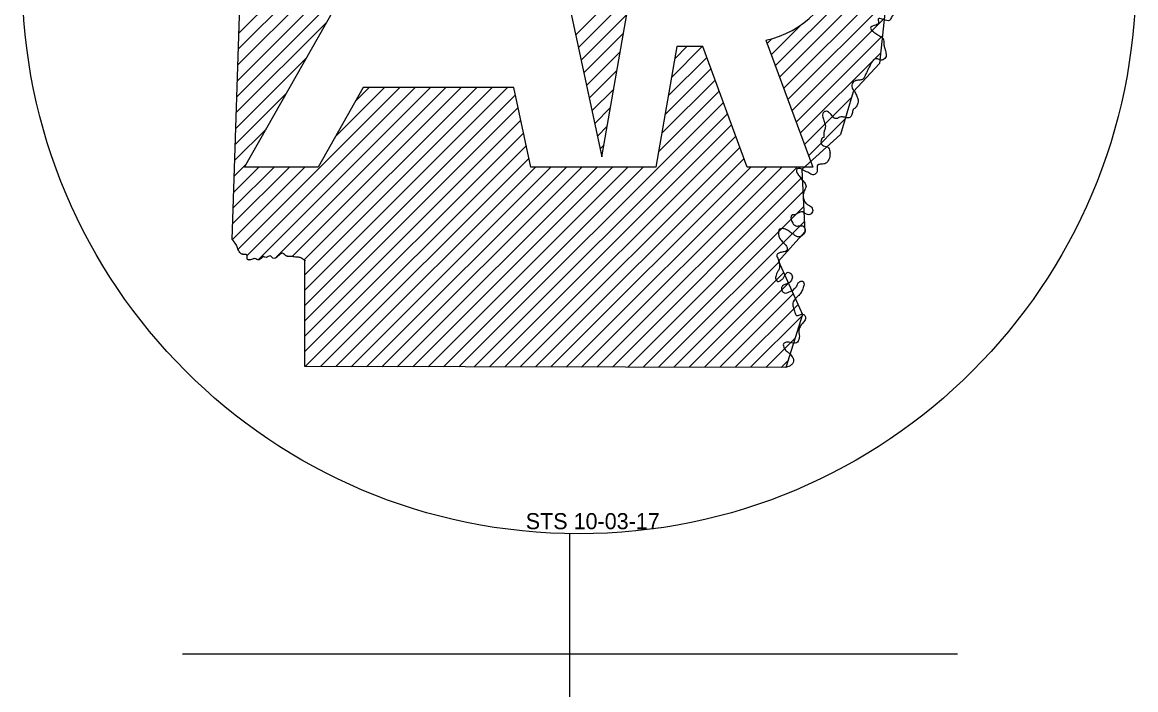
# Model space of a CAD drawing. Extents: x 6028647 to 6035072, y 5366486 to 5368495.
# Drawn here: x 6030902 to 6030966, y 5366837.7 to 5366876 of the extents above; entities that cross this region are included whole.
import ezdxf

# ---------------------------------------------------------------- set-up
doc = ezdxf.new("R2010")
doc.units = 0
doc.layers.add('R_Draft', color=7, linetype='Continuous')
doc.layers.add('R_Water Annot', color=7, linetype='Continuous')

msp = doc.modelspace()

# ---------------------------------------------------------------- linework, layer by layer
at = {"layer": 'R_Draft'}
for p, q in [((6030914.803, 5366867.71), (6030927.128, 5366889.476)), ((6030944.738, 5366875.002), (6030947.432, 5366867.71)), ((6030941.115, 5366874.633), (6030939.632, 5366874.633)), ((6030943.672, 5366867.71), (6030941.115, 5366874.633)), ((6030921.618, 5366872.277), (6030919.032, 5366867.71)), ((6030930.275, 5366872.277), (6030921.618, 5366872.277)), ((6030919.032, 5366867.71), (6030914.803, 5366867.71)), ((6030938.425, 5366867.71), (6030931.252, 5366867.71)), ((6030947.432, 5366867.71), (6030943.672, 5366867.71)), ((6030933.491, 5366765.514), (6030933.491, 5366846.638)), ((6030911.237, 5366839.743), (6030955.741, 5366839.743))]:
    msp.add_line(p, q, dxfattribs=at)
for points in [[(6030914.086, 5366863.555), (6030914.765, 5366884.006), (6030913.204, 5366896.534)], [(6030958.388, 5366891.28), (6030959.443, 5366890.179), (6030956.813, 5366888.017), (6030957.097, 5366885.835), (6030954.842, 5366884.348), (6030955.614, 5366880.992), (6030953.875, 5366879.406), (6030953.72, 5366877.681), (6030951.606, 5366876.921), (6030951.277, 5366873.668), (6030949.758, 5366872.041), (6030949.024, 5366869.591), (6030946.812, 5366867.566), (6030946.979, 5366863.993), (6030945.476, 5366862.309), (6030946.846, 5366859.243), (6030945.897, 5366856.198)], [(6030930.79, 5366889.476), (6030935.324, 5366868.292), (6030938.224, 5366884.936)], [(6030914.089, 5366863.553), (6030914.552, 5366877.585)], [(6030939.632, 5366874.633), (6030938.425, 5366867.71)], [(6030931.252, 5366867.71), (6030930.275, 5366872.277)], [(6030945.897, 5366856.198), (6030918.27, 5366856.244), (6030918.255, 5366862.342)], [(6030945.895, 5366856.195), (6030918.27, 5366856.244), (6030918.258, 5366862.343)]]:
    msp.add_lwpolyline(points, dxfattribs=at)
msp.add_ellipse((6030934.009, 5366878.608), major_axis=(31.975, 0), ratio=0.999976, dxfattribs=at)
msp.add_ellipse((6030943.601, 5366880.414), major_axis=(-5.53, 0), ratio=0.999987, start_param=1.777838, end_param=4.099264, dxfattribs=at)
for points in [[(6030952.244, 5366876.557), (6030951.982, 5366876.358), (6030951.862, 5366876.149), (6030951.192, 5366876.209), (6030951.21, 5366875.974), (6030950.971, 5366875.85), (6030950.759, 5366875.697), (6030950.88, 5366875.514), (6030951.107, 5366875.349), (6030951.334, 5366875.223), (6030951.475, 5366875.096), (6030951.511, 5366874.781), (6030951.553, 5366874.588), (6030951.627, 5366874.313), (6030951.657, 5366874.129), (6030951.521, 5366873.906), (6030951.361, 5366873.858), (6030951.199, 5366873.912), (6030951.003, 5366873.925), (6030950.845, 5366873.778), (6030950.731, 5366873.564), (6030950.62, 5366873.349), (6030950.534, 5366873.171), (6030950.445, 5366872.973), (6030950.287, 5366872.745), (6030950.086, 5366872.712), (6030949.842, 5366872.652), (6030949.698, 5366872.489), (6030949.722, 5366872.207), (6030949.857, 5366872.02), (6030949.962, 5366871.783), (6030950.034, 5366871.581), (6030950.004, 5366871.326), (6030949.898, 5366871.133), (6030949.76, 5366871.02), (6030949.698, 5366870.782), (6030949.598, 5366870.597), (6030949.51, 5366870.541), (6030949.33, 5366870.56), (6030949.135, 5366870.594), (6030948.969, 5366870.579), (6030948.812, 5366870.496), (6030948.65, 5366870.55), (6030948.484, 5366870.728), (6030948.348, 5366870.865), (6030948.197, 5366870.919), (6030948.036, 5366870.837), (6030948.012, 5366870.584), (6030948.088, 5366870.332), (6030948.154, 5366869.982), (6030948.088, 5366869.775), (6030948.065, 5366869.42)], [(6030948.065, 5366869.42), (6030948.045, 5366869.412), (6030947.911, 5366869.242), (6030947.985, 5366868.975), (6030948.279, 5366868.871), (6030948.414, 5366868.616), (6030948.421, 5366868.391), (6030948.326, 5366868.08), (6030948.188, 5366867.934), (6030947.926, 5366867.873), (6030947.724, 5366867.837), (6030947.695, 5366867.491), (6030947.6, 5366867.318), (6030947.444, 5366867.266), (6030947.216, 5366867.377), (6030947.079, 5366867.435), (6030946.915, 5366867.509), (6030946.703, 5366867.629), (6030946.542, 5366867.609), (6030946.589, 5366867.28), (6030946.604, 5366867.266), (6030946.787, 5366867.016), (6030946.963, 5366866.819), (6030947.048, 5366866.586)], [(6030948.065, 5366869.42), (6030948.045, 5366869.412), (6030947.911, 5366869.242), (6030947.985, 5366868.975), (6030948.279, 5366868.871), (6030948.414, 5366868.616), (6030948.421, 5366868.391), (6030948.326, 5366868.08), (6030948.188, 5366867.934), (6030947.926, 5366867.873), (6030947.724, 5366867.837), (6030947.695, 5366867.491), (6030947.6, 5366867.318), (6030947.444, 5366867.266), (6030947.216, 5366867.377), (6030947.079, 5366867.435), (6030946.915, 5366867.509), (6030946.703, 5366867.629), (6030946.542, 5366867.609), (6030946.589, 5366867.28), (6030946.604, 5366867.266), (6030946.787, 5366867.016), (6030946.963, 5366866.819), (6030947.048, 5366866.586)], [(6030947.048, 5366866.586), (6030946.977, 5366866.411), (6030946.889, 5366866.11), (6030946.915, 5366865.856), (6030947.03, 5366865.639), (6030947.207, 5366865.517), (6030947.408, 5366865.345), (6030947.391, 5366865.078), (6030947.275, 5366864.983), (6030947.008, 5366865.045), (6030946.806, 5366865.142), (6030946.635, 5366865.087), (6030946.406, 5366864.975), (6030946.229, 5366864.945), (6030946.236, 5366864.586), (6030946.467, 5366864.331), (6030946.67, 5366864.331), (6030946.91, 5366864.302), (6030946.991, 5366864.031), (6030946.853, 5366863.801), (6030946.629, 5366863.692), (6030946.342, 5366863.83), (6030946.14, 5366863.972), (6030945.936, 5366864.106), (6030945.681, 5366864.173), (6030945.534, 5366864.145), (6030945.467, 5366863.83), (6030945.588, 5366863.542), (6030945.781, 5366863.342), (6030945.962, 5366863.089), (6030945.936, 5366862.896), (6030945.8, 5366862.848), (6030945.557, 5366862.793), (6030945.415, 5366862.721), (6030945.379, 5366862.66), (6030945.453, 5366862.402), (6030945.518, 5366862.126), (6030945.518, 5366861.91), (6030945.436, 5366861.721), (6030945.308, 5366861.42), (6030945.324, 5366861.224), (6030945.415, 5366861.129), (6030945.527, 5366861.158), (6030945.681, 5366861.263), (6030945.777, 5366861.386), (6030945.862, 5366861.537), (6030946.016, 5366861.663), (6030946.211, 5366861.55), (6030946.258, 5366861.317), (6030946.145, 5366861.115), (6030945.986, 5366861.02), (6030945.794, 5366860.945), (6030945.648, 5366860.782), (6030945.683, 5366860.582), (6030945.8, 5366860.479), (6030946.081, 5366860.534), (6030946.264, 5366860.618), (6030946.374, 5366860.716), (6030946.5, 5366860.847), (6030946.564, 5366860.98), (6030946.666, 5366861.115), (6030946.843, 5366861.152), (6030946.924, 5366861.041), (6030946.889, 5366860.782), (6030946.787, 5366860.538), (6030946.641, 5366860.338), (6030946.485, 5366860.197), (6030946.288, 5366859.886), (6030946.328, 5366859.6), (6030946.406, 5366859.36), (6030946.503, 5366859.184), (6030946.688, 5366859.22), (6030946.889, 5366859.244), (6030947.008, 5366859.147), (6030946.998, 5366858.934), (6030946.849, 5366858.726), (6030946.703, 5366858.534), (6030946.629, 5366858.266), (6030946.66, 5366858.072), (6030946.66, 5366857.906), (6030946.599, 5366857.711), (6030946.494, 5366857.607), (6030946.211, 5366857.61), (6030945.92, 5366857.643), (6030945.763, 5366857.554), (6030945.794, 5366857.3), (6030945.962, 5366857.11), (6030946.083, 5366857.013), (6030946.258, 5366856.801), (6030946.333, 5366856.628), (6030946.312, 5366856.477), (6030946.202, 5366856.343), (6030945.895, 5366856.195)], [(6030947.048, 5366866.586), (6030946.977, 5366866.411), (6030946.889, 5366866.11), (6030946.915, 5366865.856), (6030947.03, 5366865.639), (6030947.207, 5366865.517), (6030947.408, 5366865.345), (6030947.391, 5366865.078), (6030947.275, 5366864.983), (6030947.008, 5366865.045), (6030946.806, 5366865.142), (6030946.635, 5366865.087), (6030946.406, 5366864.975), (6030946.229, 5366864.945), (6030946.236, 5366864.586), (6030946.467, 5366864.331), (6030946.67, 5366864.331), (6030946.91, 5366864.302), (6030946.991, 5366864.031), (6030946.853, 5366863.801), (6030946.629, 5366863.692), (6030946.342, 5366863.83), (6030946.14, 5366863.972), (6030945.936, 5366864.106), (6030945.681, 5366864.173), (6030945.534, 5366864.145), (6030945.467, 5366863.83), (6030945.588, 5366863.542), (6030945.781, 5366863.342), (6030945.962, 5366863.089), (6030945.936, 5366862.896), (6030945.8, 5366862.848), (6030945.557, 5366862.793), (6030945.415, 5366862.721), (6030945.379, 5366862.66), (6030945.453, 5366862.402), (6030945.518, 5366862.126), (6030945.518, 5366861.91), (6030945.436, 5366861.721), (6030945.308, 5366861.42), (6030945.324, 5366861.224), (6030945.415, 5366861.129), (6030945.527, 5366861.158), (6030945.681, 5366861.263), (6030945.777, 5366861.386), (6030945.862, 5366861.537), (6030946.016, 5366861.663), (6030946.211, 5366861.55), (6030946.258, 5366861.317), (6030946.145, 5366861.115), (6030945.986, 5366861.02), (6030945.794, 5366860.945), (6030945.648, 5366860.782), (6030945.683, 5366860.582), (6030945.8, 5366860.479), (6030946.081, 5366860.534), (6030946.264, 5366860.618), (6030946.374, 5366860.716), (6030946.5, 5366860.847), (6030946.564, 5366860.98), (6030946.666, 5366861.115), (6030946.843, 5366861.152), (6030946.924, 5366861.041), (6030946.889, 5366860.782), (6030946.787, 5366860.538), (6030946.641, 5366860.338), (6030946.485, 5366860.197), (6030946.288, 5366859.886), (6030946.328, 5366859.6), (6030946.406, 5366859.36), (6030946.503, 5366859.184), (6030946.688, 5366859.22), (6030946.889, 5366859.244), (6030947.008, 5366859.147), (6030946.998, 5366858.934), (6030946.849, 5366858.726), (6030946.703, 5366858.534), (6030946.629, 5366858.266), (6030946.66, 5366858.072), (6030946.66, 5366857.906), (6030946.599, 5366857.711), (6030946.494, 5366857.607), (6030946.211, 5366857.61), (6030945.92, 5366857.643), (6030945.763, 5366857.554), (6030945.794, 5366857.3), (6030945.962, 5366857.11), (6030946.083, 5366857.013), (6030946.258, 5366856.801), (6030946.333, 5366856.628), (6030946.312, 5366856.477), (6030946.202, 5366856.343), (6030945.895, 5366856.195)], [(6030918.255, 5366862.342), (6030918.285, 5366862.327), (6030918.142, 5366862.425), (6030917.946, 5366862.523), (6030917.727, 5366862.538), (6030917.448, 5366862.576), (6030917.215, 5366862.598), (6030916.973, 5366862.756), (6030916.717, 5366862.591), (6030916.431, 5366862.47), (6030916.265, 5366862.606), (6030916.046, 5366862.515), (6030915.896, 5366862.56), (6030915.632, 5366862.38), (6030915.383, 5366862.447), (6030915.202, 5366862.395), (6030914.976, 5366862.402), (6030914.931, 5366862.658), (6030914.712, 5366862.696), (6030914.524, 5366862.802), (6030914.395, 5366863.065), (6030914.305, 5366863.269), (6030914.086, 5366863.555)], [(6030918.258, 5366862.343), (6030918.287, 5366862.328), (6030918.144, 5366862.425), (6030917.946, 5366862.522), (6030917.725, 5366862.536), (6030917.446, 5366862.574), (6030917.213, 5366862.596), (6030916.975, 5366862.756), (6030916.721, 5366862.594), (6030916.432, 5366862.469), (6030916.265, 5366862.609), (6030916.049, 5366862.514), (6030915.895, 5366862.564), (6030915.633, 5366862.379), (6030915.38, 5366862.448), (6030915.203, 5366862.397), (6030914.978, 5366862.402), (6030914.931, 5366862.66), (6030914.71, 5366862.694), (6030914.522, 5366862.802), (6030914.396, 5366863.063), (6030914.303, 5366863.272), (6030914.089, 5366863.553)]]:
    msp.add_spline(points, degree=3, dxfattribs=at)
at = {"layer": 'R_Water Annot'}
for p, q in [((6030914.48, 5366875.412), (6030925.279, 5366886.211)), ((6030914.449, 5366874.498), (6030924.125, 5366884.174)), ((6030945.284, 5366873.525), (6030955.078, 5366883.32)), ((6030945.522, 5366872.88), (6030955.244, 5366882.602)), ((6030914.419, 5366873.584), (6030922.972, 5366882.137)), ((6030945.76, 5366872.235), (6030955.409, 5366881.883)), ((6030945.999, 5366871.59), (6030955.574, 5366881.165)), ((6030914.389, 5366872.67), (6030921.818, 5366880.1)), ((6030933.821, 5366875.315), (6030937.123, 5366878.618)), ((6030914.358, 5366871.756), (6030920.665, 5366878.063)), ((6030933.976, 5366874.588), (6030936.937, 5366877.548)), ((6030914.328, 5366870.843), (6030919.512, 5366876.026)), ((6030934.132, 5366873.86), (6030936.75, 5366876.478)), ((6030946.237, 5366870.945), (6030951.537, 5366876.245)), ((6030934.288, 5366873.132), (6030936.564, 5366875.408)), ((6030945.045, 5366874.17), (6030946.727, 5366875.852)), ((6030944.807, 5366874.816), (6030945.075, 5366875.084)), ((6030946.475, 5366870.3), (6030951.438, 5366875.262)), ((6030934.444, 5366872.404), (6030936.377, 5366874.338)), ((6030939.324, 5366872.867), (6030941.09, 5366874.633)), ((6030939.51, 5366873.937), (6030940.206, 5366874.633)), ((6030946.714, 5366869.654), (6030951.339, 5366874.279)), ((6030914.298, 5366869.929), (6030918.358, 5366873.989)), ((6030939.138, 5366871.797), (6030941.346, 5366874.006)), ((6030934.599, 5366871.676), (6030936.191, 5366873.268)), ((6030938.951, 5366870.727), (6030941.585, 5366873.361)), ((6030914.429, 5366862.991), (6030923.715, 5366872.277)), ((6030914.954, 5366862.633), (6030924.598, 5366872.277)), ((6030915.588, 5366862.384), (6030925.482, 5366872.277)), ((6030916.638, 5366862.55), (6030926.365, 5366872.277)), ((6030917.535, 5366862.564), (6030927.249, 5366872.277)), ((6030918.227, 5366862.373), (6030928.132, 5366872.277)), ((6030918.257, 5366861.519), (6030929.016, 5366872.277)), ((6030918.259, 5366860.637), (6030929.899, 5366872.277)), ((6030920.034, 5366869.48), (6030922.831, 5366872.277)), ((6030921.187, 5366871.517), (6030921.948, 5366872.277)), ((6030934.755, 5366870.949), (6030936.004, 5366872.198)), ((6030938.765, 5366869.657), (6030941.823, 5366872.715)), ((6030914.267, 5366869.015), (6030917.205, 5366871.952)), ((6030918.261, 5366859.756), (6030930.365, 5366871.859)), ((6030938.578, 5366868.587), (6030942.062, 5366872.07)), ((6030946.952, 5366869.009), (6030949.661, 5366871.718)), ((6030918.264, 5366858.875), (6030930.52, 5366871.131)), ((6030927.104, 5366856.229), (6030942.3, 5366871.425)), ((6030934.911, 5366870.221), (6030935.818, 5366871.128)), ((6030918.266, 5366857.993), (6030930.676, 5366870.404)), ((6030927.986, 5366856.228), (6030942.538, 5366870.78)), ((6030947.191, 5366868.364), (6030949.283, 5366870.457)), ((6030914.237, 5366868.101), (6030916.052, 5366869.916)), ((6030918.268, 5366857.112), (6030930.832, 5366869.676)), ((6030928.868, 5366856.226), (6030942.777, 5366870.135)), ((6030935.067, 5366869.493), (6030935.631, 5366870.058)), ((6030929.75, 5366856.225), (6030943.015, 5366869.49)), ((6030935.222, 5366868.765), (6030935.445, 5366868.988)), ((6030918.283, 5366856.244), (6030930.988, 5366868.948)), ((6030930.632, 5366856.223), (6030943.253, 5366868.845)), ((6030914.099, 5366863.546), (6030918.264, 5366867.71)), ((6030914.116, 5366864.446), (6030917.38, 5366867.71)), ((6030914.146, 5366865.36), (6030916.497, 5366867.71)), ((6030914.177, 5366866.274), (6030915.613, 5366867.71)), ((6030914.207, 5366867.187), (6030914.898, 5366867.879)), ((6030919.165, 5366856.242), (6030931.143, 5366868.22)), ((6030920.047, 5366856.241), (6030931.517, 5366867.71)), ((6030920.929, 5366856.239), (6030932.4, 5366867.71)), ((6030921.811, 5366856.238), (6030933.284, 5366867.71)), ((6030922.693, 5366856.236), (6030934.167, 5366867.71)), ((6030923.575, 5366856.235), (6030935.051, 5366867.71)), ((6030924.457, 5366856.233), (6030935.934, 5366867.71)), ((6030925.339, 5366856.232), (6030936.818, 5366867.71)), ((6030926.222, 5366856.231), (6030937.702, 5366867.71)), ((6030931.514, 5366856.222), (6030943.492, 5366868.199)), ((6030932.396, 5366856.22), (6030943.886, 5366867.71)), ((6030933.278, 5366856.219), (6030944.77, 5366867.71)), ((6030934.16, 5366856.218), (6030945.653, 5366867.71)), ((6030935.042, 5366856.216), (6030946.537, 5366867.71)), ((6030935.924, 5366856.215), (6030946.832, 5366867.122)), ((6030936.807, 5366856.213), (6030946.872, 5366866.279)), ((6030937.689, 5366856.212), (6030946.912, 5366865.435)), ((6030938.571, 5366856.21), (6030946.951, 5366864.591)), ((6030939.453, 5366856.209), (6030945.5, 5366862.256)), ((6030940.335, 5366856.207), (6030945.773, 5366861.645)), ((6030941.217, 5366856.206), (6030946.046, 5366861.035)), ((6030942.099, 5366856.205), (6030946.318, 5366860.424)), ((6030942.981, 5366856.203), (6030946.591, 5366859.813)), ((6030943.863, 5366856.202), (6030946.819, 5366859.158)), ((6030944.745, 5366856.2), (6030946.419, 5366857.874)), ((6030945.627, 5366856.199), (6030946.02, 5366856.591))]:
    msp.add_line(p, q, dxfattribs=at)

# ---------------------------------------------------------------- texts
at = {"layer": 'R_Draft'}
msp.add_text('STS 10-03-17', height=0.92446, dxfattribs=at).set_placement((6030930.95, 5366846.896))

doc.saveas('drawing.dxf')
